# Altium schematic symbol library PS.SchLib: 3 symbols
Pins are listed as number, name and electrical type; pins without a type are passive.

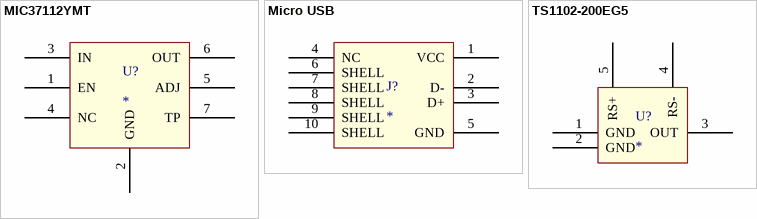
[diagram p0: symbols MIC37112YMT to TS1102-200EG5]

## MIC37112YMT
designator U?
LDO, 1A
pins: 1 EN, 2 GND, 3 IN, 4 NC, 5 ADJ, 6 OUT, 7 TP

## Micro USB
designator J?
type B
pins: 1 VCC, 2 D-, 3 D+, 4 NC, 5 GND, 6 SHELL, 7 SHELL, 8 SHELL, 9 SHELL, 10 SHELL

## TS1102-200EG5
designator U?
High Side Current Monitor, 200 V/V
pins: 1 GND, 2 GND, 3 OUT, 4 RS-, 5 RS+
